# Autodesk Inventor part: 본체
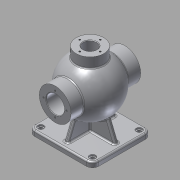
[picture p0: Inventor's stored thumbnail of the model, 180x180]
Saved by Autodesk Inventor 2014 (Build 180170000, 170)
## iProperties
Created: 2015-10
Part Number: 본체
Material: Aluminum 6061
Document SubType Name: Modeling
Designer: youjin04
Density: 2.71 g/cm^3
Appearance: Aluminum - Flat
Mass: 1509.55 g
Surface Area: 1153.8 cm^2
Volume: 557.028 cm^3
Author: youjin04
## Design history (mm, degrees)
sketch "Sketch1"
  geometry: L1 (-62.5, 57.5)-(62.5, 57.5); L2 (62.5, 57.5)-(62.5, -57.5); L3 (62.5, -57.5)-(-62.5, -57.5); L4 (-62.5, -57.5)-(-62.5, 57.5); L5 (-62.5, 57.5)-(62.5, -57.5); L6 (62.5, 57.5)-(-62.5, -57.5); 3 further points
  constraints: 12 end point, 3 midpoint, 2 parallel, 1 coincident, 1 horizontal, 1 perpendicular
  dimensions: "d0" = 125 distance of L2.end L3.end; "d1" = 115 distance of L1.end L2.end
extrude "Extrusion1" new body sketch "Sketch1" distance "d2" = 10; taper "d3" = 0 deg
fillet "Fillet1" dims "d4" = 12
sketch "Sketch2" dims "d5" = 53
  geometry: L1 (40.677, 118.976)-(-40.677, 51.024); A1 r 53 centre (0, 85) between (40.677, 118.976) and (-40.677, 51.024); 2 further points
  constraints: 2 end point, 2 point on circle, 1 centre point, 1 coincident, 1 midpoint, 1 vertical alignment, 4 other
  dimensions: "d6" = 85 distance of point (0, 0) point (0, 85)
revolve "Revolution1" sketch "Sketch2" stored, may be unused: angle "d7" = 90 deg
sketch "Sketch3"
  geometry: C1 r 31 at (0, 85); 1 further point
  constraints: 1 centre point, 1 vertical alignment
  dimensions: "d8" = 62 diameter of C1; "d9" = 85 distance of point (0, 0) C1.centre
extrude "Extrusion2" join sketch "Sketch3" stored distance "d10" = 136; taper "d11" = 0 deg
workplane "Work Plane1"
sketch "Sketch4"
  geometry: C1 r 27 at (0, 0); 1 further point
  constraints: 1 centre point, 1 coincident
  dimensions: "d13" = 54 diameter of C1
extrude "Extrusion3" join sketch "Sketch4" stored distance "d14" = 136; taper "d15" = 0 deg
sketch "Sketch5" dims "d16" = 43
  geometry: L1 (37.568, 105.92)-(-37.568, 64.08); A1 r 43 centre (0, 85) between (37.568, 105.92) and (-37.568, 64.08); 2 further points
  constraints: 2 end point, 2 point on circle, 1 centre point, 1 coincident, 1 midpoint, 1 vertical alignment, 4 other
  dimensions: "d17" = 85 distance of point (0, 0) point (0, 85)
revolve "Revolution2" sketch "Sketch5" stored, may be unused: angle "d18" = 90 deg
sketch "Sketch6"
  geometry: C1 r 31 at (0, 0) reference; C2 r 17.5 at (0, 0); 1 further point
  constraints: 1 centre point, 1 coincident
  dimensions: "d19" = 35 diameter of C2
extrude "Extrusion4" cut sketch "Sketch6" stored distance "d20" = 136; taper "d21" = 0 deg
sketch "Sketch7"
  geometry: C1 r 27 at (0, 0) reference; C2 r 13 at (0, 0)
  constraints: 1 centre point, 1 coincident
  dimensions: "d22" = 26 diameter of C2
extrude "Extrusion5" cut sketch "Sketch7" stored distance "d23" = 0; taper "d24" = 0 deg
workplane "Work Plane2"
sketch "Sketch8"
  geometry: L1 (50.5, 85)-(-50.5, 85) reference; C1 r 18.5 at (0, 0); 1 further point
  constraints: 1 centre point, 1 vertical alignment
  dimensions: "d26" = 37 diameter of C1; "d27" = 85 distance from line of L1 C1.centre
extrude "Extrusion6" cut sketch "Sketch8" distance "d28" = 1.75; taper "d29" = 0 deg
workplane "Work Plane3"
sketch "Sketch11"
  geometry: L1 (-27, 150)-(27, 150) reference; L2 (-27, 150)-(-27, 130.607) reference; 2 further points
  constraints: 1 other
  dimensions: "d57" = 10 distance from line of L1 point (0, 140); "d58" = 27 distance from line of point (0, 140) L2
emboss "Emboss1" sketch "Sketch11" dims "d0" = 125, "d1" = 115, "d8" = 62, "d59" = 0.5, "d60" = 0
sketch "Sketch12"
  geometry: C1 r 17.5 at (0, 0) reference; C2 r 31 at (0, 0) reference; A1 r 22.5 centre (0, 0) between (0, 22.5) and (0, -22.5); 3 further points
  constraints: 4 point on circle, 2 horizontal alignment, 2 vertical alignment, 1 centre point, 1 coincident
  dimensions: "d61" = 45 diameter of A1
hole "Hole1" sketch "Sketch12" at (0, 22.5), (22.5, 0), (0, -22.5), (-22.5, 0) diameter "d62" = 3.242; stored, may be unused: countersink angle "d66" = 90 deg, drill point angle "d68" = 118 deg; dims "d63" = 12, "d64" = 4, "d65" = 2, "d67" = 15
sketch "Sketch13"
  geometry: C1 r 13 at (0, 0) reference; C2 r 27 at (0, 0) reference; A1 r 20 centre (0, 0) between (0, 20) and (20, 0); 2 further points
  constraints: 4 point on circle, 2 horizontal alignment, 2 vertical alignment, 1 centre point, 1 coincident
  dimensions: "d69" = 40 diameter of A1
hole "Hole2" sketch "Sketch13" at (0, 20), (20, 0), (0, -20), (-20, 0) diameter "d70" = 3.242; stored, may be unused: countersink angle "d74" = 90 deg, drill point angle "d76" = 118 deg; dims "d71" = 9, "d72" = 4, "d73" = 2, "d75" = 11
sketch "Sketch14"
  geometry: C1 r 17.5 at (0, 0) reference; C2 r 31 at (0, 0) reference; A1 r 24 centre (0, 0) between (0, 24) and (-24, 0); 3 further points
  constraints: 4 point on circle, 2 horizontal alignment, 2 vertical alignment, 1 centre point, 1 coincident
  dimensions: "d77" = 48 diameter of A1
hole "Hole3" sketch "Sketch14" at (0, 24), (24, 0), (0, -24), (-24, 0) diameter "d78" = 3.242; stored, may be unused: countersink angle "d82" = 90 deg, drill point angle "d84" = 118 deg; dims "d79" = 16, "d80" = 4, "d81" = 2, "d83" = 19
sketch "Sketch15"
  geometry: 5 further points
  dimensions: "d85" = 101 distance of point (-50.5, 45.5) point (50.5, 45.5); "d86" = 91 distance of point (50.5, -45.5) point (50.5, 45.5); "d87" = 50.5 horizontal distance of point (0, 0) point (50.5, 45.5); "d88" = 45.5 vertical distance of point (0, 0) point (50.5, -45.5); "d89" = 91 distance of point (-50.5, 45.5) point (-50.5, -45.5); "d90" = 45.5 vertical distance of point (0, 0) point (-50.5, -45.5); "d91" = 101 distance of point (-50.5, -45.5) point (50.5, -45.5); "d92" = 50.5 horizontal distance of point (0, 0) point (-50.5, -45.5)
hole "Hole4" sketch "Sketch15" at (-50.5, 45.5), (50.5, 45.5), (50.5, -45.5), (-50.5, -45.5) diameter "d93" = 8; stored, may be unused: countersink angle "d97" = 90 deg, drill point angle "d99" = 0 deg; dims "d94" = 16, "d95" = 12, "d96" = 3, "d98" = 10
fillet "Fillet2" dims "d100" = 3
sketch "Sketch16"
  geometry: L1 (-33.719, 44.109)-(-47.5, 10); L2 (-57.5, 0)-(-57.5, 10) reference; L3 (-68, 54)-(-44.497, 54) reference; L4 (44.497, 54)-(68, 54) reference; L5 (39.5, 10)-(51.5, 10) reference; L6 (45.5, 10)-(-45.5, 10) reference; L7 (45.5, 10)-(57.5, 10) reference; L8 (57.5, 10)-(57.5, 0) reference; L9 (-51.5, 10)-(-39.5, 10) reference; L10 (-57.5, 10)-(-45.5, 10) reference; L11 (33.719, 44.109)-(47.5, 10); L12 (-33.719, 44.109)-(-16.247, 44.109); L13 (16.247, 44.109)-(33.719, 44.109); A1 r 53 centre (0, 85) between (42.113, 117.179) and (42.113, 52.821) reference; A2 r 3 centre (-44.497, 51) between (-42.113, 52.821) and (-44.497, 54) reference; A3 r 3 centre (44.497, 51) between (44.497, 54) and (42.113, 52.821) reference; A4 r 53 centre (0, 85) between (-33.719, 44.109) and (33.719, 44.109); A5 r 44 centre (0, 85) between (-16.247, 44.109) and (16.247, 44.109); 1 further point
  constraints: 8 end point, 6 point on circle, 2 centre point, 2 coincident, 2 point on line, 1 concentric
  dimensions: "d103" = 10 distance from line of L2 L1.end; "d104" = 22 deg angle of L2 L1; "d105" = 10 distance of L7.end L11.end; "d107" = 22 deg angle of L11 L8; "d108" = 88 diameter of A5; "d109" = 112 deg angle of L1 L12; "d110" = 112 deg angle of L13 L11
feature "Rib4" sketch "Sketch16" dims "d111" = 1, "d112" = 8, "d113" = 0, "d114" = 0, "d115" = 1, "d116" = 1
sketch "Sketch17"
  geometry: L1 (-37.379, 47.426)-(-52.5, 10); L2 (37.379, 47.426)-(52.5, 10); L3 (-62.5, 0)-(-62.5, 10) reference; L4 (50.5, 10)-(-50.5, 10) reference; L5 (-62.5, 10)-(-50.5, 10) reference; L6 (50.5, 10)-(62.5, 10) reference; L7 (62.5, 10)-(62.5, 0) reference; A1 r 53 centre (0, 85) between (-28.393, 129.753) and (28.393, 129.753) reference; 1 further point
  constraints: 4 end point, 2 point on circle, 2 point on line
  dimensions: "d117" = 10 distance from line of L3 L1.end; "d118" = 22 deg angle of L3 L1; "d119" = 10 distance from line of L7 L2.end; "d120" = 22 deg angle of L2 L7
feature "Rib5" dims "d121" = 1, "d122" = 8, "d123" = 0, "d124" = 0, "d125" = 1, "d126" = 1
feature "Rib6" dims "d127" = 1, "d128" = 8, "d129" = 0, "d130" = 0, "d131" = 1, "d132" = 1
fillet "Fillet5" dims "d133" = 3
fillet "Fillet6" dims "d134" = 3
fillet "Fillet7" dims "d135" = 3
chamfer "Chamfer1" distance "d137" = 1; stored, may be unused: second distance "d138" = 2, angle "d139" = 45 deg
fillet "Fillet9" dims "d140" = 3
fillet "Fillet10" dims "d141" = 3
body "Solid1"
other parameters: "d25" = -16, "d56" = -27, "d106" = 22 deg
